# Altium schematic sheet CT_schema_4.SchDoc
size 282 x 169 mm
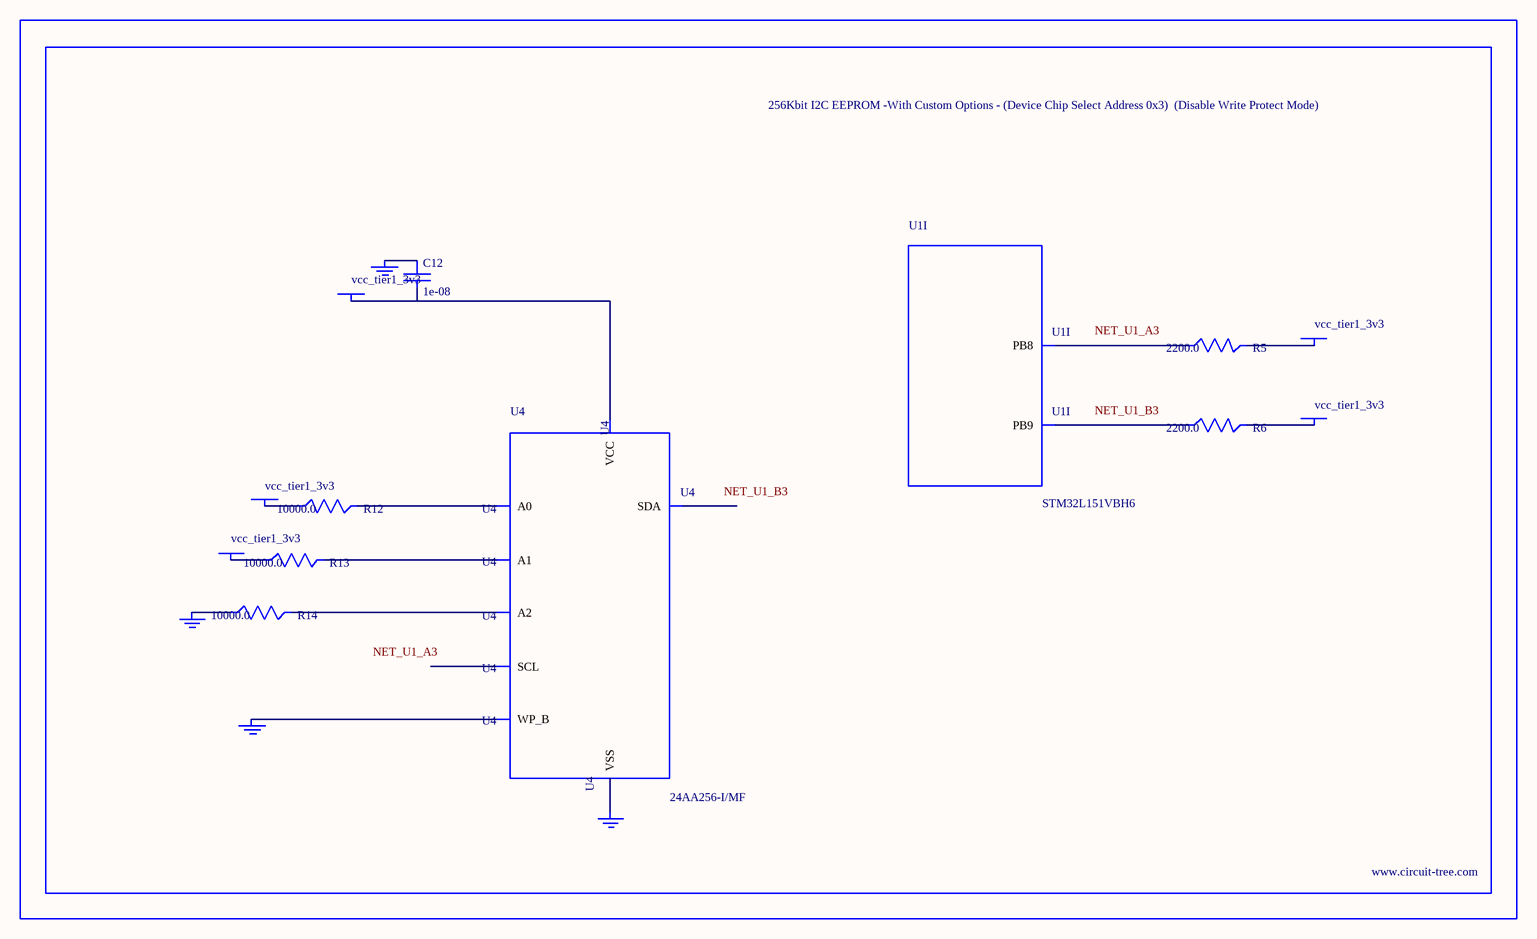
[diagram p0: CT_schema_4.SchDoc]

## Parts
BORDER3  (no value)
C12  1e-08  [C0402]
GND_INSTANCE_3_0  (no value)
GND_INSTANCE_3_1  (no value)
GND_INSTANCE_3_2  (no value)
GND_INSTANCE_3_3  (no value)
POWER_INSTANCE_3_0  vcc_tier1_3v3
POWER_INSTANCE_3_1  vcc_tier1_3v3
POWER_INSTANCE_3_2  vcc_tier1_3v3
POWER_INSTANCE_3_3  vcc_tier1_3v3
POWER_INSTANCE_3_4  vcc_tier1_3v3
R5  2200.0  [R0603]
R6  2200.0  [R0603]
R12  10000.0  [R0603]
R13  10000.0  [R0603]
R14  10000.0  [R0603]
U1  STM32L151VBH6  [UFBGA100]  (part I of 9)
U4  24AA256-I/MF  [DFN8-S]

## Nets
NetC12_1: C12.1 GND_INSTANCE_3_2.0(GND)
NetC12_2: C12.2 POWER_INSTANCE_3_2.0(PWR) U4.8(VCC)
NetGND_INSTANCE_3_0_0: GND_INSTANCE_3_0.0(GND) R14.1
NetGND_INSTANCE_3_1_0: GND_INSTANCE_3_1.0(GND) U4.7(WP_B)
NetGND_INSTANCE_3_3_0: GND_INSTANCE_3_3.0(GND) U4.4(VSS)
NetPOWER_INSTANCE_3_0_0: POWER_INSTANCE_3_0.0(PWR) R12.1
NetPOWER_INSTANCE_3_1_0: POWER_INSTANCE_3_1.0(PWR) R13.1
NetPOWER_INSTANCE_3_3_0: POWER_INSTANCE_3_3.0(PWR) R5.2
NetPOWER_INSTANCE_3_4_0: POWER_INSTANCE_3_4.0(PWR) R6.2
NetR5_1: R5.1 U1.A3(PB8)
NetR6_1: R6.1 U1.B3(PB9)
NetR12_2: R12.2 U4.1(A0)
NetR13_2: R13.2 U4.2(A1)
NetR14_2: R14.2 U4.3(A2)

Not connected (* = marked no-connect by the designer): U4 5(SDA) 6(SCL)

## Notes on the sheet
- Labels drawn without touching a wire or pin: NET_U1_A3, NET_U1_B3

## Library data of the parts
BORDER3 = BORDER_PAGE3
C12 = C0402C103K3RAC
GND_INSTANCE_3_0-GND_INSTANCE_3_3 = GND
POWER_INSTANCE_3_0-POWER_INSTANCE_3_4 = PWR
R5 R6 = RC0603JR-072K2L
R12-R14 = RC0603JR-0710KL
